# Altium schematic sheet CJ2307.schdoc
size 127 x 101 mm
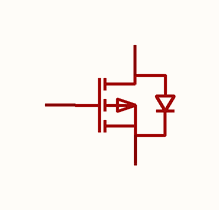
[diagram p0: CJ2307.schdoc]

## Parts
Q?  cj2307  [SOT-23-3_L2.9-W1.3-P1.90-LS2.4-BR]  (value not drawn)

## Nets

Not connected (* = marked no-connect by the designer): Q? 1(G) 2(S) 3(D)

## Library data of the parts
Q? = cj2307: 数量:1个P沟道;漏源电压(Vdss):30V;连续漏极电流(Id):2.7A;导通电阻(RDS(on)):138mΩ@4.5V;耗散功率(Pd):1.1W;阈值电压(Vgs(th)):1V;; Manufacturer: CJ(江苏长电/长晶); AddInBom: yes; ModelId: c62791f0466c4ae2a892c056b845b0ca; ModelName: SOT-23-3P_L2.9-W1.3-H1.0-LS2.4-P0.95; ModelTransform: 98.425,114.173,0,180,0,0,0.0005,-0.0005,0; Number: 1个P沟道; Drain to Source Voltage: 30V; Current - Continuous Drain(Id): 2.7A; Pd - Power Dissipation: 1.1W; Gate Threshold Voltage (Vgs(th)): 1V; Gate Charge(Qg): 6.2nC@4.5V; Input Capacitance(Ciss): 340pF; Reverse Transfer Capacitance (Crss@Vds): 51pF; Type: P沟道; Output Capacitance(Coss): 67pF; Vgs: ±20V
